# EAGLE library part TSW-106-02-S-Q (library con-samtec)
THROUGH-HOLE .025" SQ POST HEADER Source: Samtec TSW.pdf
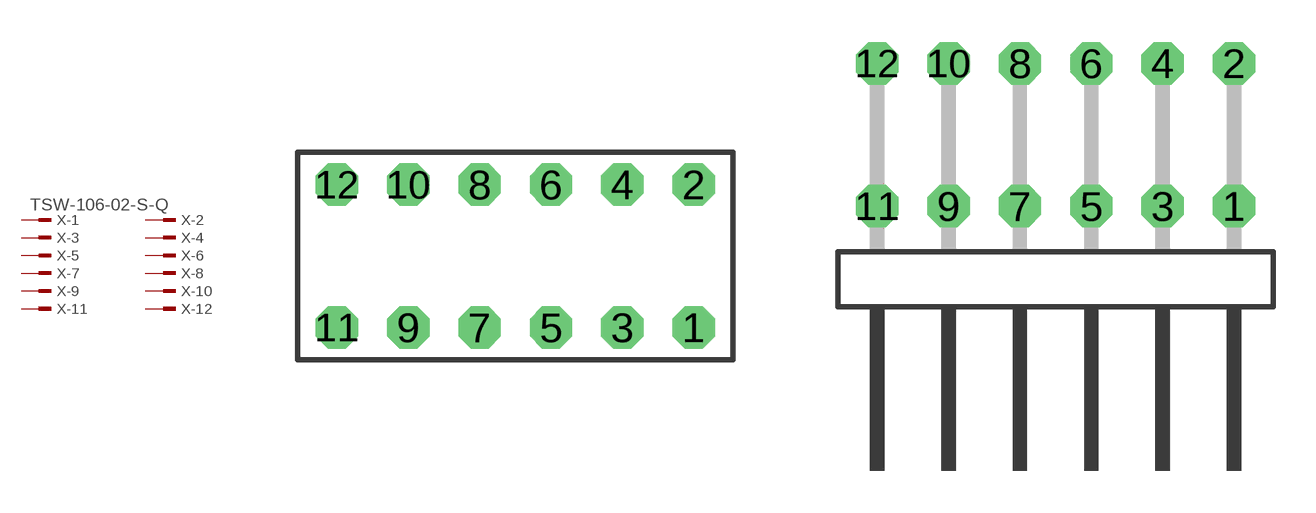
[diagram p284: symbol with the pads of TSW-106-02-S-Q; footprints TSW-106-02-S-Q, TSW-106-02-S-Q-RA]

Designator prefix X; gates -1=MPINV -2=MPIN -3=MPIN -4=MPIN -5=MPIN -6=MPIN -7=MPIN -8=MPIN -9=MPIN -10=MPIN -11=MPIN -12=MPIN

## TSW-106-02-S-Q (OC_FARNELL: unknown; OC_NEWARK: unknown)  [TSW-106-02-S-Q]
1  -1:1  pas
2  -2:1  pas
3  -3:1  pas
4  -4:1  pas
5  -5:1  pas
6  -6:1  pas
7  -7:1  pas
8  -8:1  pas
9  -9:1  pas
10  -10:1  pas
11  -11:1  pas
12  -12:1  pas

## TSW-106-02-S-Q-RA (OC_FARNELL: unknown; OC_NEWARK: unknown)  [TSW-106-02-S-Q-RA]
Pads as for TSW-106-02-S-Q

## Footprint TSW-106-02-S-Q (pad centres in mm)
THROUGH-HOLE .025" SQ POST HEADER Source: Samtec TSW.pdf
drill 1 pad 1.5 octagon: 1 6.35,-2.54; 2 6.35,2.54; 3 3.81,-2.54; 4 3.81,2.54; 5 1.27,-2.54; 6 1.27,2.54; 7 -1.27,-2.54; 8 -1.27,2.54; 9 -3.81,-2.54; 10 -3.81,2.54; 11 -6.35,-2.54; 12 -6.35,2.54

## Footprint TSW-106-02-S-Q-RA (pad centres in mm)
THROUGH-HOLE .025" SQ POST HEADER Source: Samtec TSW.pdf
drill 1 pad 1.5 octagon: 1 6.35,1.524; 2 6.35,6.604; 3 3.81,1.524; 4 3.81,6.604; 5 1.27,1.524; 6 1.27,6.604; 7 -1.27,1.524; 8 -1.27,6.604; 9 -3.81,1.524; 10 -3.81,6.604; 11 -6.35,1.524; 12 -6.35,6.604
